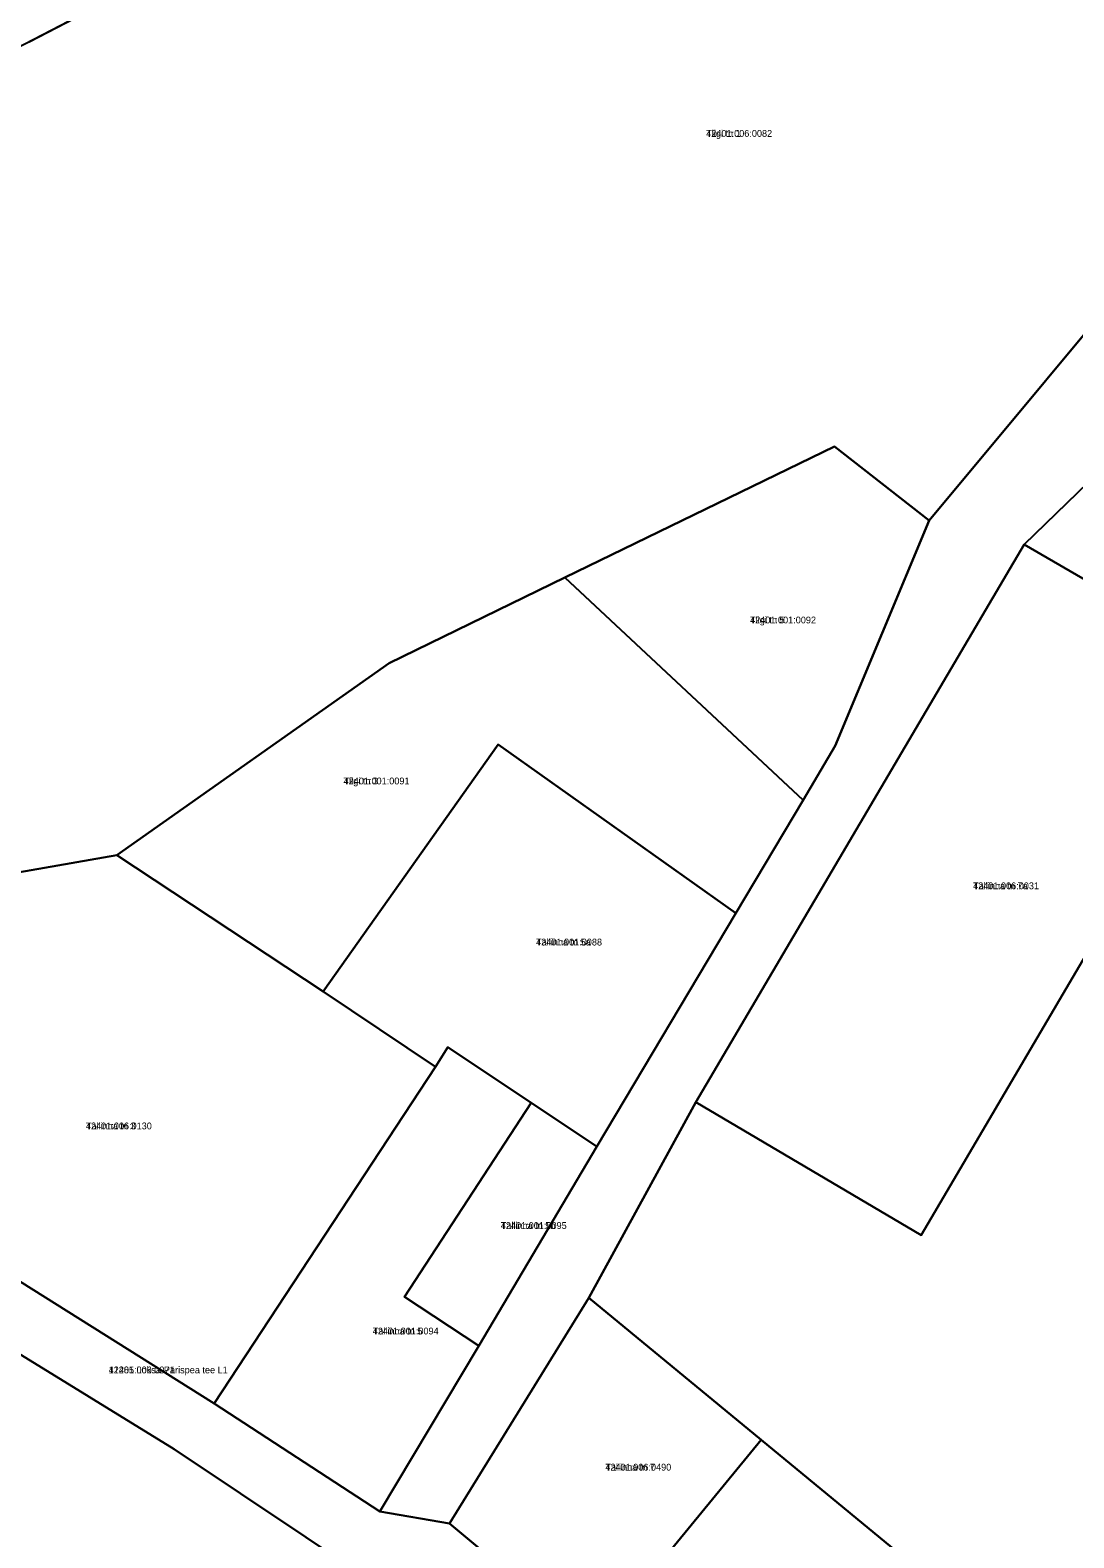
# Model space of a CAD drawing. Extents: x 595979 to 597983, y 6604231 to 6607350.
# Drawn here: x 596644 to 596873.6, y 6606552.8 to 6606884.7 of the extents above; entities that cross this region are included whole.
import ezdxf

# ---------------------------------------------------------------- set-up
doc = ezdxf.new("R2010")
doc.units = 0
for name, color, linetype in [('L_AADRESS', 7, 'Continuous'), ('PIIR', 7, 'Continuous'), ('TUNNUS', 7, 'Continuous')]:
    doc.layers.add(name, color=color, linetype=linetype)

msp = doc.modelspace()

# ---------------------------------------------------------------- linework, layer by layer
at = {"layer": 'PIIR'}
for points in [[(596909.1, 6606385.61), (596872.46, 6606418.2), (596861.56, 6606419.99), (596848.55, 6606432.38), (596762.79, 6606514.09), (596675.69, 6606572.34), (596638.27, 6606595.39), (596557.11, 6606645.51), (596555.44, 6606646.42), (596542.85, 6606653.57), (596526.52, 6606663), (596451.2, 6606705.15), (596442.76, 6606730.14), (596437.35, 6606745.96), (596437.73, 6606810.5), (596437.33, 6606810.61), (596437.96, 6606836.91), (596442.64, 6606872.04), (596470.43, 6606959.84)], [(596643.75, 6606882.19), (596697.35, 6606910.02)], [(596464.47, 6606887.4), (596457.38, 6606863.19), (596452.59, 6606835.16), (596451.96, 6606809.89), (596451.4, 6606745.94), (596455.33, 6606728.96), (596461.16, 6606718.64), (596465.96, 6606712.4), (596556.83, 6606658.51), (596558.45, 6606661.57), (596684.47, 6606582.41), (596720.93, 6606558.63), (596736.24, 6606555.98), (596767.98, 6606529.52), (596797.47, 6606504.22), (596834.39, 6606472.9), (596889.22, 6606422.58)], [(596893.34, 6606838.71), (596841.73, 6606776.77), (596820.91, 6606793.06), (596761.61, 6606764.25), (596722.97, 6606745.37), (596663.04, 6606703.09), (596606.42, 6606693.19)], [(596925.85, 6606832.78), (596862.67, 6606771.48), (596790.45, 6606648.77), (596766.91, 6606605.63), (596736.24, 6606555.98), (596720.93, 6606558.63), (596742.65, 6606595.12), (596768.66, 6606639), (596799.22, 6606690.36), (596814, 6606715.21), (596821.08, 6606727.17), (596841.73, 6606776.77), (596893.34, 6606838.71)], [(596902.6, 6606512.44), (596855.64, 6606498.37), (596871.06, 6606516.85), (596834.82, 6606549.67), (596804.78, 6606574.42), (596766.91, 6606605.63), (596790.45, 6606648.77), (596840.01, 6606619.43), (596912.39, 6606742.64), (596862.67, 6606771.48), (596925.85, 6606832.78)]]:
    msp.add_lwpolyline(points, dxfattribs=at)
for points in [[(596552.73, 6606890.18), (596558.1, 6606891.54), (596623.21, 6606907.76), (596659.33, 6606937.04), (596677.69, 6606947.28), (596694.97, 6606954.79), (596697.35, 6606910.02), (596631, 6606875.52), (596634.38, 6606847.12), (596631.03, 6606832.78), (596620.92, 6606827.47), (596596.63, 6606830.4)], [(596814, 6606715.21), (596761.61, 6606764.25), (596820.91, 6606793.06), (596841.73, 6606776.77), (596821.08, 6606727.17)], [(596912.39, 6606742.64), (596840.01, 6606619.43), (596790.45, 6606648.77), (596862.67, 6606771.48)], [(596708.41, 6606673.12), (596663.04, 6606703.09), (596722.97, 6606745.37), (596761.61, 6606764.25), (596814, 6606715.21), (596799.22, 6606690.36), (596746.93, 6606727.46)], [(596733.13, 6606656.54), (596708.41, 6606673.12), (596746.93, 6606727.46), (596799.22, 6606690.36), (596768.66, 6606639), (596754.22, 6606648.61), (596735.89, 6606660.85)], [(596733.13, 6606656.54), (596684.47, 6606582.41), (596558.45, 6606661.57), (596566.37, 6606676.82), (596606.42, 6606693.19), (596663.04, 6606703.09), (596708.41, 6606673.12)], [(596720.93, 6606558.63), (596684.47, 6606582.41), (596733.13, 6606656.54), (596735.89, 6606660.85), (596754.22, 6606648.61), (596726.36, 6606605.87), (596742.65, 6606595.12)], [(596742.65, 6606595.12), (596726.36, 6606605.87), (596754.22, 6606648.61), (596768.66, 6606639)], [(596736.24, 6606555.98), (596766.91, 6606605.63), (596804.78, 6606574.42), (596767.98, 6606529.52)], [(596634.48, 6606573.71), (596638.27, 6606595.39), (596675.69, 6606572.34), (596762.79, 6606514.09), (596848.55, 6606432.38), (596831.88, 6606435.78), (596800.52, 6606462.81), (596786.69, 6606477.58), (596763.58, 6606493.7), (596758.19, 6606494.47), (596739.8, 6606366.49), (596720.28, 6606342.66), (596569.74, 6606364.59), (596577.35, 6606416.75), (596577.86, 6606420.2), (596578.99, 6606421.05), (596609.49, 6606416.58), (596622.09, 6606502.86), (596630.11, 6606548.73)], [(596767.98, 6606529.52), (596804.78, 6606574.42), (596834.82, 6606549.67), (596797.47, 6606504.22)]]:
    msp.add_lwpolyline(points, close=True, dxfattribs=at)

# ---------------------------------------------------------------- texts
at = {"layer": 'L_AADRESS'}
for s, p in [('Tiigi tn 1', (596792.71, 6606861.24)), ('Tiigi tn 5', (596802.36, 6606754.13)), ('Tiigi tn 3', (596712.93, 6606718.69)), ('Tallinna tn 7a', (596851.42, 6606695.61)), ('Tallinna tn 5a', (596755.28, 6606683.23)), ('Tallinna tn 3', (596656.24, 6606642.75)), ('Tallinna tn 5b', (596747.51, 6606620.82)), ('Tallinna tn 5', (596719.34, 6606597.6)), ('11285 Loksa-Pärispea tee L1', (596661.24, 6606589.04)), ('Tallinna tn 7', (596770.51, 6606567.63))]:
    msp.add_text(s, height=1.5, dxfattribs=at).set_placement(p)
at = {"layer": 'TUNNUS'}
for s, p in [('42401:006:0082', (596792.71, 6606861.24)), ('42401:001:0092', (596802.36, 6606754.13)), ('42401:001:0091', (596712.93, 6606718.69)), ('42401:006:0031', (596851.42, 6606695.61)), ('42401:001:0088', (596755.28, 6606683.23)), ('42401:006:0130', (596656.24, 6606642.75)), ('42401:001:0095', (596747.51, 6606620.82)), ('42401:001:0094', (596719.34, 6606597.6)), ('42401:006:0071', (596661.24, 6606589.04)), ('42401:006:0490', (596770.51, 6606567.63))]:
    msp.add_text(s, height=1.5, dxfattribs=at).set_placement(p)

doc.saveas('drawing.dxf')
